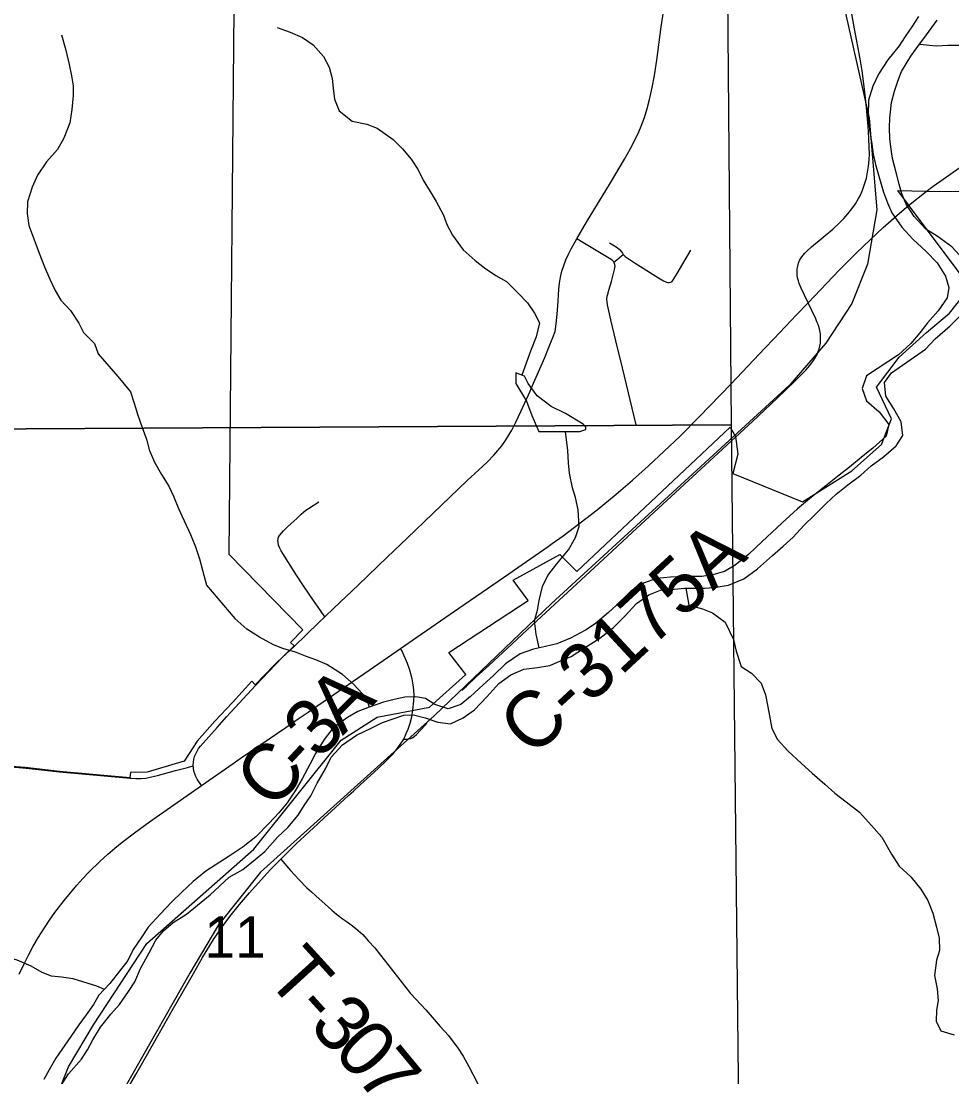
# Model space of a CAD drawing. Extents: x 0 to 34, y 0 to 22.
# Drawn here: x 2.385 to 3.328, y 15.071 to 16.14 of the extents above; entities that cross this region are included whole.
import ezdxf

# ---------------------------------------------------------------- set-up
doc = ezdxf.new("R2010")
doc.units = 0
for name, color, linetype in [('GM_X_County_Road', 7, 'Continuous'), ('GM_X_County_Road_Text', 7, 'Continuous'), ('GM_X_County_Text', 7, 'Continuous'), ('GM_X_Interchange_Ramps', 7, 'Continuous'), ('GM_X_Minor_River_Text', 7, 'Continuous'), ('GM_X_Section_Text', 7, 'Continuous'), ('GM_X_State_Location', 7, 'Continuous'), ('GM_X_State_Route', 7, 'Continuous'), ('GM_X_State_Shield', 7, 'Continuous'), ('GM_X_Township_Road', 7, 'Continuous'), ('GM_X_Township_Text', 7, 'Continuous')]:
    doc.layers.add(name, color=color, linetype=linetype)

msp = doc.modelspace()

# ---------------------------------------------------------------- linework, layer by layer
at = {"layer": 'GM_X_County_Road'}
msp.add_line((3.2844, 15.9533), (3.3022, 15.9674), dxfattribs=at)
for points in [[(3.3022, 15.9674), (3.3093, 15.9728), (3.3228, 15.9822), (3.3508, 16.0019), (3.3633, 16.0111), (3.373, 16.0188), (3.38, 16.0248), (3.3868, 16.0312), (3.3933, 16.0378), (3.3995, 16.0447), (3.4052, 16.052), (3.4106, 16.0596), (3.4156, 16.0674), (3.4164, 16.0689), (3.4201, 16.0755), (3.4242, 16.0838), (3.4279, 16.0923), (3.4312, 16.101), (3.4341, 16.1098), (3.4365, 16.1188), (3.4378, 16.1248), (3.4389, 16.1309), (3.4401, 16.1401)], [(3.148, 15.8183), (3.171, 15.8426), (3.1826, 15.8547), (3.214, 15.8876), (3.2315, 15.9053), (3.245, 15.9182), (3.2587, 15.9309), (3.2751, 15.9453), (3.2844, 15.9533)], [(2.3833, 15.1744), (2.3886, 15.1856), (2.3928, 15.1939), (2.3976, 15.2028), (2.403, 15.2119), (2.4091, 15.2216), (2.4142, 15.2294), (2.4196, 15.237), (2.4291, 15.2492), (2.437, 15.259), (2.4417, 15.2648), (2.4478, 15.2716), (2.4542, 15.2782), (2.4651, 15.2888), (2.4733, 15.296), (2.4803, 15.3023), (2.4876, 15.3083), (2.5001, 15.3179), (2.5153, 15.329), (2.5681, 15.3656), (2.6003, 15.3879), (2.6074, 15.393), (2.6283, 15.4072), (2.6534, 15.4244), (2.666, 15.4331), (2.676, 15.4399), (2.7477, 15.4893), (2.7698, 15.5045), (2.7861, 15.5158), (2.8245, 15.5422), (2.8794, 15.5802), (2.8885, 15.5865), (2.9192, 15.6077), (2.9234, 15.6107), (2.9343, 15.6186), (2.9517, 15.6317), (2.9688, 15.6451), (2.988, 15.6609), (3.0046, 15.675), (3.0209, 15.6894), (3.0368, 15.7042), (3.0525, 15.7193), (3.0722, 15.7392), (3.1047, 15.7726), (3.1389, 15.8087), (3.148, 15.8183)]]:
    msp.add_lwpolyline(points, dxfattribs=at)
at = {"layer": 'GM_X_County_Road_Text'}
for points in [[(3.2957, 16.1168), (3.3124, 16.1151), (3.3242, 16.1155), (3.3435, 16.1156), (3.353, 16.1153), (3.3901, 16.1154), (3.4011, 16.1147), (3.4151, 16.1128), (3.4254, 16.1114), (3.4367, 16.1099), (3.4519, 16.1092), (3.4678, 16.1085), (3.4936, 16.1086), (3.5035, 16.1082), (3.5133, 16.1087), (3.5254, 16.1121), (3.5375, 16.1213), (3.5431, 16.1334), (3.5476, 16.1452)], [(2.6446, 16.1334), (2.6579, 16.1289), (2.6704, 16.1233), (2.6811, 16.1161), (2.6917, 16.104), (2.6975, 16.0934), (2.7005, 16.082), (2.7013, 16.0722), (2.7029, 16.0608), (2.7075, 16.049), (2.7208, 16.0385), (2.7356, 16.0355), (2.7462, 16.0314), (2.7622, 16.02), (2.7717, 16.0106), (2.7805, 16), (2.7877, 15.9894), (2.7927, 15.9788), (2.7996, 15.9674), (2.8057, 15.9572), (2.8133, 15.9436), (2.8167, 15.9341), (2.8225, 15.9231), (2.8332, 15.9084), (2.8453, 15.8974), (2.8548, 15.8902), (2.8662, 15.8823), (2.8769, 15.8763), (2.889, 15.8645), (2.8982, 15.8547), (2.9054, 15.8441), (2.9104, 15.8343), (2.907, 15.8202), (2.9014, 15.8058), (2.8926, 15.7813)], [(2.4262, 16.1261), (2.4307, 16.1105), (2.4341, 16.0961), (2.4364, 16.0847), (2.4379, 16.0744), (2.4379, 16.0645), (2.4367, 16.0505), (2.4348, 16.0368), (2.4287, 16.0216), (2.4223, 16.0099), (2.4109, 15.9973), (2.4021, 15.9841), (2.3964, 15.9719), (2.3918, 15.9571), (2.3915, 15.945), (2.3933, 15.9328), (2.3983, 15.9195), (2.4036, 15.9051), (2.4089, 15.891), (2.4145, 15.8785), (2.4198, 15.8671), (2.4255, 15.8572), (2.4354, 15.847), (2.4437, 15.8341), (2.4486, 15.8246), (2.4596, 15.8135), (2.4634, 15.8029)], [(2.4634, 15.8029), (2.4832, 15.78), (2.4961, 15.7645), (2.4999, 15.7531), (2.5037, 15.741), (2.5079, 15.7284), (2.5128, 15.7156), (2.5151, 15.7057), (2.5204, 15.6932), (2.5277, 15.6807), (2.5349, 15.669), (2.5398, 15.6587), (2.5448, 15.6462), (2.5505, 15.6337), (2.5569, 15.6201), (2.5619, 15.6076), (2.566, 15.5954), (2.5691, 15.5837), (2.5733, 15.5685), (2.6017, 15.5348)], [(2.9103, 15.5051), (2.9071, 15.519), (2.9054, 15.5326), (2.9084, 15.5433), (2.9102, 15.5532), (2.9135, 15.5672), (2.919, 15.5783), (2.928, 15.5901), (2.9397, 15.6043), (2.9471, 15.6169), (2.9505, 15.6279), (2.9495, 15.645), (2.9468, 15.6575), (2.944, 15.6673), (2.9409, 15.6821), (2.94, 15.6927), (2.9391, 15.7052), (2.9368, 15.7244)], [(3.0587, 15.5655), (3.0619, 15.5485), (3.0756, 15.5448), (3.0859, 15.5407), (3.0985, 15.531), (3.107, 15.5136), (3.1097, 15.5019), (3.1148, 15.4864), (3.1251, 15.4796), (3.135, 15.4695), (3.1393, 15.4574), (3.1417, 15.4453), (3.1457, 15.4233), (3.1515, 15.4123), (3.1622, 15.4007), (3.176, 15.3879), (3.1867, 15.3781), (3.1997, 15.3669), (3.2096, 15.3579), (3.2211, 15.3492), (3.2348, 15.3387), (3.2467, 15.3252), (3.2574, 15.3132), (3.267, 15.2962), (3.2747, 15.2841), (3.2866, 15.2732), (3.2969, 15.2608), (3.3039, 15.2491), (3.3089, 15.2362), (3.3128, 15.2222), (3.3152, 15.2112), (3.3157, 15.1987), (3.3128, 15.1888), (3.3106, 15.1733), (3.3134, 15.1596), (3.3143, 15.1479), (3.3128, 15.138), (3.3122, 15.127), (3.3172, 15.1172), (3.3305, 15.1131)], [(2.7384, 15.4451), (2.7351, 15.454), (2.7225, 15.468), (2.711, 15.4781), (2.695, 15.4882), (2.6839, 15.493), (2.6733, 15.4967), (2.6634, 15.5008), (2.6505, 15.5045), (2.641, 15.5082), (2.6269, 15.516), (2.6139, 15.5242), (2.6017, 15.5348)], [(2.4697, 15.1592), (2.4619, 15.1623), (2.4478, 15.1668), (2.438, 15.1699), (2.4262, 15.1714), (2.416, 15.1725), (2.4065, 15.1763), (2.3955, 15.1827), (2.3815, 15.1887), (2.3712, 15.1918), (2.3561, 15.1955), (2.3451, 15.2035), (2.336, 15.2175), (2.331, 15.2281), (2.3223, 15.2387), (2.3094, 15.2501), (2.2973, 15.2553), (2.2836, 15.2568), (2.2719, 15.2591), (2.2643, 15.2716), (2.2639, 15.2948)]]:
    msp.add_lwpolyline(points, dxfattribs=at)
at = {"layer": 'GM_X_County_Text'}
msp.add_lwpolyline([(3.171, 16.3684), (3.2444, 16.0416), (3.2521, 15.9488), (3.2426, 15.8938), (3.2268, 15.854), (3.2005, 15.8138), (3.1642, 15.7716), (2.9225, 15.55), (2.8037, 15.4363), (2.6278, 15.2778), (2.5854, 15.2245), (2.5564, 15.1755), (2.4633, 15.0123)], dxfattribs=at)
at = {"layer": 'GM_X_Interchange_Ramps'}
for points in [[(2.3717, 15.3848), (2.3903, 15.3831), (2.4089, 15.3812), (2.4243, 15.3794), (2.4958, 15.373), (2.4967, 15.373)], [(2.4967, 15.373), (2.5015, 15.3728), (2.5071, 15.3728), (2.5116, 15.3731), (2.5173, 15.3743), (2.5235, 15.3758), (2.5418, 15.3808), (2.5539, 15.384), (2.5598, 15.3855)], [(2.6483, 15.2911), (2.6581, 15.2797), (2.6669, 15.2702), (2.6749, 15.2621), (2.6794, 15.2579), (2.684, 15.2538), (2.6932, 15.2455), (2.7001, 15.2394), (2.7049, 15.2355), (2.7073, 15.2335), (2.7097, 15.2317), (2.7147, 15.2281), (2.7198, 15.2246), (2.7245, 15.2208), (2.7316, 15.2146), (2.7374, 15.208), (2.7436, 15.2011), (2.7494, 15.1939), (2.7531, 15.189), (2.7605, 15.1797), (2.7799, 15.1551), (2.7902, 15.1437), (2.7954, 15.1383), (2.8017, 15.1309), (2.81, 15.1216), (2.8182, 15.1124), (2.8282, 15.0994), (2.8331, 15.0916), (2.839, 15.081), (2.8432, 15.0726), (2.8531, 15.0536)]]:
    msp.add_lwpolyline(points, dxfattribs=at)
at = {"layer": 'GM_X_Minor_River_Text'}
for points in [[(2.9548, 15.7316), (2.9368, 15.7424), (2.9224, 15.7496), (2.908, 15.7604), (2.899, 15.773), (2.8954, 15.7802), (2.8864, 15.7838), (2.8864, 15.773), (2.8972, 15.755), (2.9026, 15.7406), (2.9098, 15.7244)], [(2.9098, 15.7244), (2.9512, 15.7244)], [(2.9512, 15.7244), (2.9575, 15.7264), (2.9575, 15.7287), (2.9548, 15.7316)]]:
    msp.add_lwpolyline(points, dxfattribs=at)
at = {"layer": 'GM_X_State_Route'}
for points in [[(2.1086, 16.7183), (3.0962, 16.7214), (3.1048, 15.7312), (2.0927, 15.7254)], [(2.0927, 15.7254), (3.1048, 15.7312), (3.1155, 14.7229), (2.1005, 14.722)]]:
    msp.add_lwpolyline(points, close=True, dxfattribs=at)
for points in [[(2.6016, 16.2256), (2.5958, 15.6001), (2.6707, 15.5235), (2.6581, 15.5105), (2.6618, 15.5071), (2.6424, 15.4884), (2.6226, 15.4677), (2.6191, 15.4713), (2.5994, 15.4499), (2.5815, 15.431), (2.5636, 15.4106), (2.5555, 15.398), (2.5505, 15.3904), (2.5132, 15.3791), (2.496, 15.3787), (2.4956, 15.3736), (2.4241, 15.38), (2.3894, 15.3838), (2.356, 15.3864)], [(2.9483, 15.9193), (2.9582, 15.9362), (2.9823, 15.9762), (2.9967, 16.0002), (3.0028, 16.0111), (3.0071, 16.0194), (3.0112, 16.0279), (3.0136, 16.0336), (3.0169, 16.0424), (3.0197, 16.0514), (3.022, 16.0605), (3.0247, 16.0727), (3.0269, 16.0849), (3.0293, 16.1003), (3.0339, 16.1343), (3.0386, 16.165)], [(3.1826, 15.8547), (3.1789, 15.8625), (3.1756, 15.8695), (3.1736, 15.8741), (3.1727, 15.8769), (3.1719, 15.8799), (3.1715, 15.8829), (3.1714, 15.8859), (3.1716, 15.8889), (3.1721, 15.8919), (3.1729, 15.8948), (3.174, 15.8975), (3.1755, 15.9001), (3.1772, 15.9026), (3.1792, 15.9049), (3.1813, 15.9071), (3.186, 15.9112), (3.198, 15.921), (3.2076, 15.9291), (3.2145, 15.9355), (3.2189, 15.94), (3.223, 15.9447), (3.2269, 15.9497), (3.2305, 15.9549), (3.2337, 15.9603), (3.2352, 15.9631), (3.2377, 15.9688), (3.2398, 15.9748), (3.2416, 15.9808), (3.2429, 15.9869), (3.2439, 15.9932), (3.2444, 15.9994), (3.2447, 16.0057), (3.2446, 16.0119), (3.2442, 16.0213), (3.2434, 16.0337), (3.2418, 16.0524), (3.2397, 16.071), (3.2372, 16.0895), (3.2353, 16.1017), (3.2297, 16.1321), (3.2242, 16.1628)], [(2.3902, 14.972), (2.4333, 15.0808), (2.4585, 15.1232), (2.5126, 15.2055), (2.621, 15.3012), (2.7097, 15.4117), (2.7462, 15.435), (2.7991, 15.4451), (2.8357, 15.4782), (2.8187, 15.5005), (2.8991, 15.5532), (2.8839, 15.5737), (2.9312, 15.5996), (2.9482, 15.5826), (3.1038, 15.7286), (3.109, 15.7192), (3.1115, 15.7014), (3.1064, 15.6818), (3.1769, 15.6529), (3.2268, 15.6844), (3.2571, 15.7112), (3.267, 15.7371), (3.2518, 15.7692), (3.275, 15.7997), (3.3027, 15.8246), (3.3259, 15.8442), (3.3468, 15.8704), (3.2842, 15.9538), (3.2736, 15.9684), (3.302, 15.9679), (3.4757, 15.9666)], [(3.0083, 15.7312), (2.9944, 15.7888), (2.9877, 15.8161), (2.9826, 15.8373), (2.9793, 15.8525), (2.9789, 15.8555), (2.9788, 15.8585), (2.9792, 15.8615), (2.9799, 15.8645), (2.9807, 15.8674), (2.9833, 15.8764), (2.9866, 15.8885), (2.987, 15.8918), (2.9868, 15.8935), (2.9862, 15.8952), (2.9858, 15.8959), (2.9853, 15.8966), (2.984, 15.8978), (2.9813, 15.8996), (2.9678, 15.9076), (2.9544, 15.9156), (2.9483, 15.9193)], [(2.9813, 15.9154), (2.9866, 15.9123), (2.9891, 15.9106), (2.9915, 15.9086), (2.9936, 15.9064), (2.9944, 15.9051), (2.9952, 15.9036)], [(2.9858, 15.8959), (2.9888, 15.8983), (2.9934, 15.9021), (2.9952, 15.9036)], [(2.9952, 15.9036), (2.9961, 15.9026), (2.9972, 15.9015), (3.0074, 15.8947), (3.0127, 15.8915), (3.0284, 15.8817), (3.031, 15.88), (3.0362, 15.8768), (3.039, 15.8755), (3.0405, 15.8752), (3.042, 15.8751), (3.0435, 15.8756), (3.0448, 15.8764), (3.0467, 15.8788), (3.0498, 15.8842), (3.0638, 15.9081)], [(2.6929, 15.5365), (2.6885, 15.5429), (2.6815, 15.553), (2.6722, 15.5668), (2.6637, 15.5797), (2.6505, 15.6006), (2.6489, 15.6033), (2.6474, 15.6061), (2.6462, 15.6091), (2.6456, 15.6123), (2.6455, 15.6139), (2.6457, 15.6156), (2.6462, 15.6171), (2.647, 15.6188), (2.649, 15.6213), (2.651, 15.6236), (2.6555, 15.628), (2.6645, 15.6363), (2.669, 15.6406), (2.6738, 15.6446), (2.6764, 15.6464), (2.6869, 15.653)]]:
    msp.add_lwpolyline(points, dxfattribs=at)
at = {"layer": 'GM_X_State_Shield'}
for points in [[(3.2945, 16.1446), (3.2885, 16.1351), (3.2809, 16.1245), (3.2749, 16.115), (3.2632, 16.1009), (3.2538, 16.0864), (3.2482, 16.0742), (3.2437, 16.0598), (3.2434, 16.0443), (3.2449, 16.0302), (3.2473, 16.0154), (3.2485, 16.0052), (3.2508, 15.9949), (3.2542, 15.9828), (3.2589, 15.9669), (3.2631, 15.9559), (3.2673, 15.9457), (3.2776, 15.9313), (3.2886, 15.9192), (3.3023, 15.9067), (3.3134, 15.895), (3.3218, 15.8818), (3.3252, 15.87), (3.3234, 15.8597), (3.3143, 15.8464), (3.3034, 15.8342), (3.2958, 15.8244), (3.2868, 15.8133), (3.274, 15.8019)], [(3.3399, 15.8985), (3.3281, 15.9114), (3.3132, 15.9223), (3.3018, 15.9291), (3.29, 15.942), (3.282, 15.9545), (3.2774, 15.9651), (3.2747, 15.9749), (3.272, 15.9852), (3.2682, 16.0007), (3.2666, 16.0102), (3.2655, 16.0208), (3.265, 16.0318), (3.2654, 16.0421), (3.2672, 16.0576), (3.2702, 16.069), (3.2735, 16.0793), (3.2773, 16.0888), (3.2867, 16.1044), (3.2939, 16.1143), (3.3025, 16.1261), (3.3134, 16.1409)], [(3.3016, 15.8077), (3.3114, 15.8183), (3.3265, 15.8313), (3.339, 15.8439)], [(2.596, 15.2729), (2.61, 15.2806), (2.6224, 15.2906), (2.6322, 15.2987), (2.645, 15.3132), (2.6555, 15.3232), (2.666, 15.3358), (2.672, 15.3453), (2.6787, 15.3552), (2.6854, 15.3682), (2.6937, 15.3827), (2.6996, 15.3945), (2.7109, 15.4068), (2.7252, 15.4168), (2.7399, 15.4237), (2.7513, 15.4295), (2.7611, 15.433), (2.7732, 15.4369), (2.783, 15.4374), (2.7948, 15.4341), (2.8074, 15.4297), (2.8203, 15.4283), (2.8331, 15.4341), (2.8448, 15.4425), (2.8572, 15.4555), (2.8692, 15.4689), (2.8816, 15.4778), (2.8945, 15.4836), (2.9085, 15.4852), (2.921, 15.4872), (2.9312, 15.4915), (2.9425, 15.4965), (2.9561, 15.505), (2.9716, 15.515), (2.9851, 15.5254), (2.9968, 15.5373), (3.0088, 15.5499), (3.0212, 15.5587), (3.0329, 15.5634), (3.0432, 15.5643), (3.0576, 15.5655), (3.0777, 15.5657), (3.0871, 15.5662), (3.1019, 15.5686), (3.1174, 15.5752), (3.1313, 15.5852), (3.1464, 15.5986), (3.1573, 15.6082), (3.1675, 15.6174), (3.1784, 15.6289), (3.1893, 15.64), (3.2009, 15.6515), (3.2111, 15.6607), (3.2227, 15.6703), (3.2359, 15.6802), (3.2465, 15.6894), (3.2589, 15.6987), (3.2717, 15.7098), (3.2784, 15.7201), (3.2768, 15.7341), (3.2694, 15.7473), (3.2614, 15.7602), (3.2601, 15.7738), (3.2672, 15.7837), (3.3016, 15.8077)], [(3.274, 15.8019), (3.2418, 15.7808), (3.2374, 15.7679), (3.2417, 15.7554), (3.2547, 15.7442), (3.2643, 15.7313), (3.2617, 15.7196), (3.2482, 15.7073), (3.2384, 15.6996), (3.2245, 15.6881), (3.2139, 15.68), (3.2004, 15.6693), (3.1861, 15.6578), (3.1718, 15.6459), (3.1563, 15.6317), (3.1458, 15.6221), (3.136, 15.6129), (3.1225, 15.5999), (3.1086, 15.5888), (3.098, 15.5826), (3.087, 15.5795), (3.0749, 15.5774), (3.0556, 15.5773), (3.0431, 15.5768), (3.029, 15.5755), (3.0158, 15.5708), (3.003, 15.5624), (2.9921, 15.5516), (2.9804, 15.5409), (2.9669, 15.5294), (2.9571, 15.5229), (2.942, 15.5148), (2.928, 15.5093), (2.9167, 15.5066), (2.9045, 15.5038), (2.8909, 15.4991), (2.8762, 15.4891), (2.8638, 15.4772), (2.8533, 15.4676), (2.8405, 15.4558), (2.8307, 15.4477), (2.8179, 15.4434), (2.8046, 15.4478), (2.795, 15.4538), (2.7851, 15.4556), (2.7742, 15.4552), (2.7632, 15.4528), (2.7526, 15.45), (2.7378, 15.445), (2.7265, 15.4407), (2.7159, 15.4345), (2.7016, 15.4241), (2.6922, 15.4123), (2.6837, 15.3982), (2.6781, 15.3875), (2.6702, 15.3726), (2.6628, 15.3604), (2.6549, 15.3482), (2.6463, 15.3379), (2.6365, 15.3275), (2.623, 15.3138), (2.6102, 15.3034), (2.5962, 15.2942)], [(2.5962, 15.2942), (2.5724, 15.2789), (2.5596, 15.2686), (2.5482, 15.2576), (2.538, 15.2477), (2.5262, 15.2352), (2.5141, 15.2223), (2.5077, 15.2124), (2.499, 15.1995), (2.4933, 15.1885), (2.4827, 15.1745), (2.4751, 15.165), (2.4642, 15.1532), (2.4585, 15.1437), (2.4513, 15.1335), (2.4437, 15.1232), (2.4358, 15.1115), (2.4206, 15.0895), (2.4138, 15.0777), (2.4085, 15.0678)], [(2.4263, 15.0625), (2.4332, 15.0736), (2.4464, 15.0884), (2.4525, 15.0978), (2.4581, 15.1081), (2.4657, 15.121), (2.4763, 15.1339), (2.485, 15.1438), (2.4941, 15.1571), (2.5005, 15.1669), (2.5062, 15.1802), (2.5149, 15.1961), (2.5217, 15.209), (2.5297, 15.2185), (2.5395, 15.2269), (2.5528, 15.2352), (2.5641, 15.2444), (2.577, 15.255), (2.596, 15.2729)]]:
    msp.add_lwpolyline(points, dxfattribs=at)
at = {"layer": 'GM_X_Township_Road'}
for points in [[(2.9158, 15.7991), (2.9197, 15.8087), (2.9239, 15.8196), (2.9262, 15.8257), (2.9275, 15.8333), (2.9285, 15.8432), (2.9295, 15.8563), (2.9302, 15.8686), (2.9308, 15.8747), (2.9318, 15.8807), (2.9332, 15.8867), (2.935, 15.8926), (2.9372, 15.8983), (2.9397, 15.904), (2.9425, 15.9094), (2.9456, 15.9148), (2.9483, 15.9193)], [(3.1092, 15.7186), (3.1264, 15.7345), (3.1512, 15.7581), (3.1691, 15.7753), (3.1803, 15.7863), (3.1843, 15.7912), (3.188, 15.7962), (3.1897, 15.7989), (3.1913, 15.8017), (3.1926, 15.8046), (3.1937, 15.8076), (3.1945, 15.8107), (3.195, 15.8138), (3.1953, 15.817), (3.1953, 15.8202), (3.1951, 15.8233), (3.1945, 15.8265), (3.1938, 15.8296), (3.1928, 15.8326), (3.1916, 15.8355), (3.1903, 15.8384), (3.1863, 15.8469), (3.1826, 15.8547)], [(2.8798, 15.7211), (2.8824, 15.7258), (2.8866, 15.7337), (2.892, 15.7451), (2.901, 15.7651), (2.9022, 15.7678), (2.9109, 15.7878), (2.9158, 15.7991)], [(2.8023, 15.6411), (2.8372, 15.6745), (2.8486, 15.6851), (2.8577, 15.6936), (2.8643, 15.7003), (2.8684, 15.705), (2.8723, 15.7099), (2.8759, 15.7151), (2.8798, 15.7211)], [(2.8464, 15.4756), (2.8592, 15.4874), (2.8779, 15.5047), (2.8981, 15.5234), (2.9079, 15.5324), (2.9842, 15.6032), (3.0047, 15.6223), (3.1092, 15.7186)], [(2.6929, 15.5365), (2.7023, 15.5454), (2.727, 15.5691), (2.7562, 15.597), (2.7764, 15.6164), (2.8023, 15.6411)], [(2.662, 15.5066), (2.6866, 15.5303), (2.6929, 15.5365)], [(2.6228, 15.4671), (2.6363, 15.4813), (2.6499, 15.4952), (2.662, 15.5066)], [(2.7823, 15.4419), (2.7832, 15.4513), (2.7834, 15.4569), (2.7831, 15.4626), (2.7824, 15.4677), (2.7814, 15.4739), (2.779, 15.4826), (2.7766, 15.4893), (2.7747, 15.4939), (2.773, 15.4978), (2.7712, 15.5019), (2.7698, 15.5045)], [(2.8319, 15.4624), (2.8364, 15.4663), (2.8464, 15.4756)], [(2.5839, 15.4243), (2.5935, 15.4354), (2.6061, 15.4492), (2.6228, 15.4671)], [(2.773, 15.4127), (2.7754, 15.4184), (2.7773, 15.4228), (2.7795, 15.4289), (2.7812, 15.4352), (2.7823, 15.4419)], [(2.5598, 15.3855), (2.5597, 15.3862), (2.5599, 15.3892), (2.5603, 15.3922), (2.5611, 15.395), (2.5622, 15.3978), (2.5636, 15.4005), (2.5652, 15.403), (2.5671, 15.4054), (2.5839, 15.4243)], [(2.773, 15.4127), (2.7759, 15.4127), (2.7781, 15.4128), (2.7801, 15.4133), (2.7821, 15.4143), (2.7835, 15.4153), (2.7858, 15.4174), (2.7942, 15.4266), (2.7965, 15.4287)], [(2.6483, 15.2911), (2.6581, 15.3008), (2.6641, 15.3065), (2.6858, 15.3267), (2.6927, 15.3333), (2.6995, 15.3394), (2.7174, 15.356), (2.7219, 15.3601), (2.7287, 15.3664), (2.7426, 15.3788), (2.7538, 15.3892), (2.7619, 15.3975), (2.7656, 15.402), (2.7693, 15.4072), (2.773, 15.4127)], [(2.5681, 15.3656), (2.5638, 15.372), (2.5624, 15.3747), (2.5612, 15.3774), (2.5604, 15.3803), (2.5599, 15.3832), (2.5598, 15.3855)], [(2.4606, 14.9996), (2.4708, 15.0187), (2.4844, 15.0431), (2.5014, 15.0728), (2.5122, 15.0918), (2.5385, 15.1377), (2.5601, 15.1753), (2.5691, 15.1916), (2.5803, 15.2097), (2.5893, 15.223), (2.5969, 15.2329), (2.6066, 15.2452), (2.6166, 15.2568), (2.6377, 15.2802), (2.6483, 15.2911)]]:
    msp.add_lwpolyline(points, dxfattribs=at)

# ---------------------------------------------------------------- texts
at = {"layer": 'GM_X_Section_Text'}
for s, height, rotation, p in [('C-3175A', 0.05682, 42.7822, (2.903, 15.3929)), ('A', 0.0568, 45.1494, (2.7111, 15.4157)), ('3', 0.0568, 46.1666, (2.687, 15.3906)), ('C', 0.0568, 47.8741, (2.6401, 15.3393)), ('-', 0.0568, 47.0316, (2.6713, 15.3737))]:
    msp.add_text(s, height=height, rotation=rotation, dxfattribs=at).set_placement(p)
at = {"layer": 'GM_X_State_Location'}
msp.add_text('11', height=0.04186, rotation=0, dxfattribs=at).set_placement((2.571, 15.1912))
at = {"layer": 'GM_X_Township_Text'}
for s, rotation, p in [('T', 312.3019, (2.6316, 15.1703)), ('-', 312.3, (2.6602, 15.1389)), ('3', 312.3757, (2.676, 15.1216)), ('0', 312.9585, (2.7, 15.0953)), ('7', 309.6343, (2.7233, 15.0703))]:
    msp.add_text(s, height=0.0568, rotation=rotation, dxfattribs=at).set_placement(p)

doc.saveas('drawing.dxf')
